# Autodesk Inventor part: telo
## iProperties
Created: 2010-03
Part Number: telo
Document SubType Name: Modeling
Designer: Ondra
Density: 2.71 g/cm^3
Material: Aluminum-6061
Mass: 1.23481 g
Surface Area: 6.35869 cm^2
Volume: 0.45565 cm^3
Author: Ondra
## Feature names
1. Revolution1
2. Revolution2
3. Extrusion2
4. Hole2
